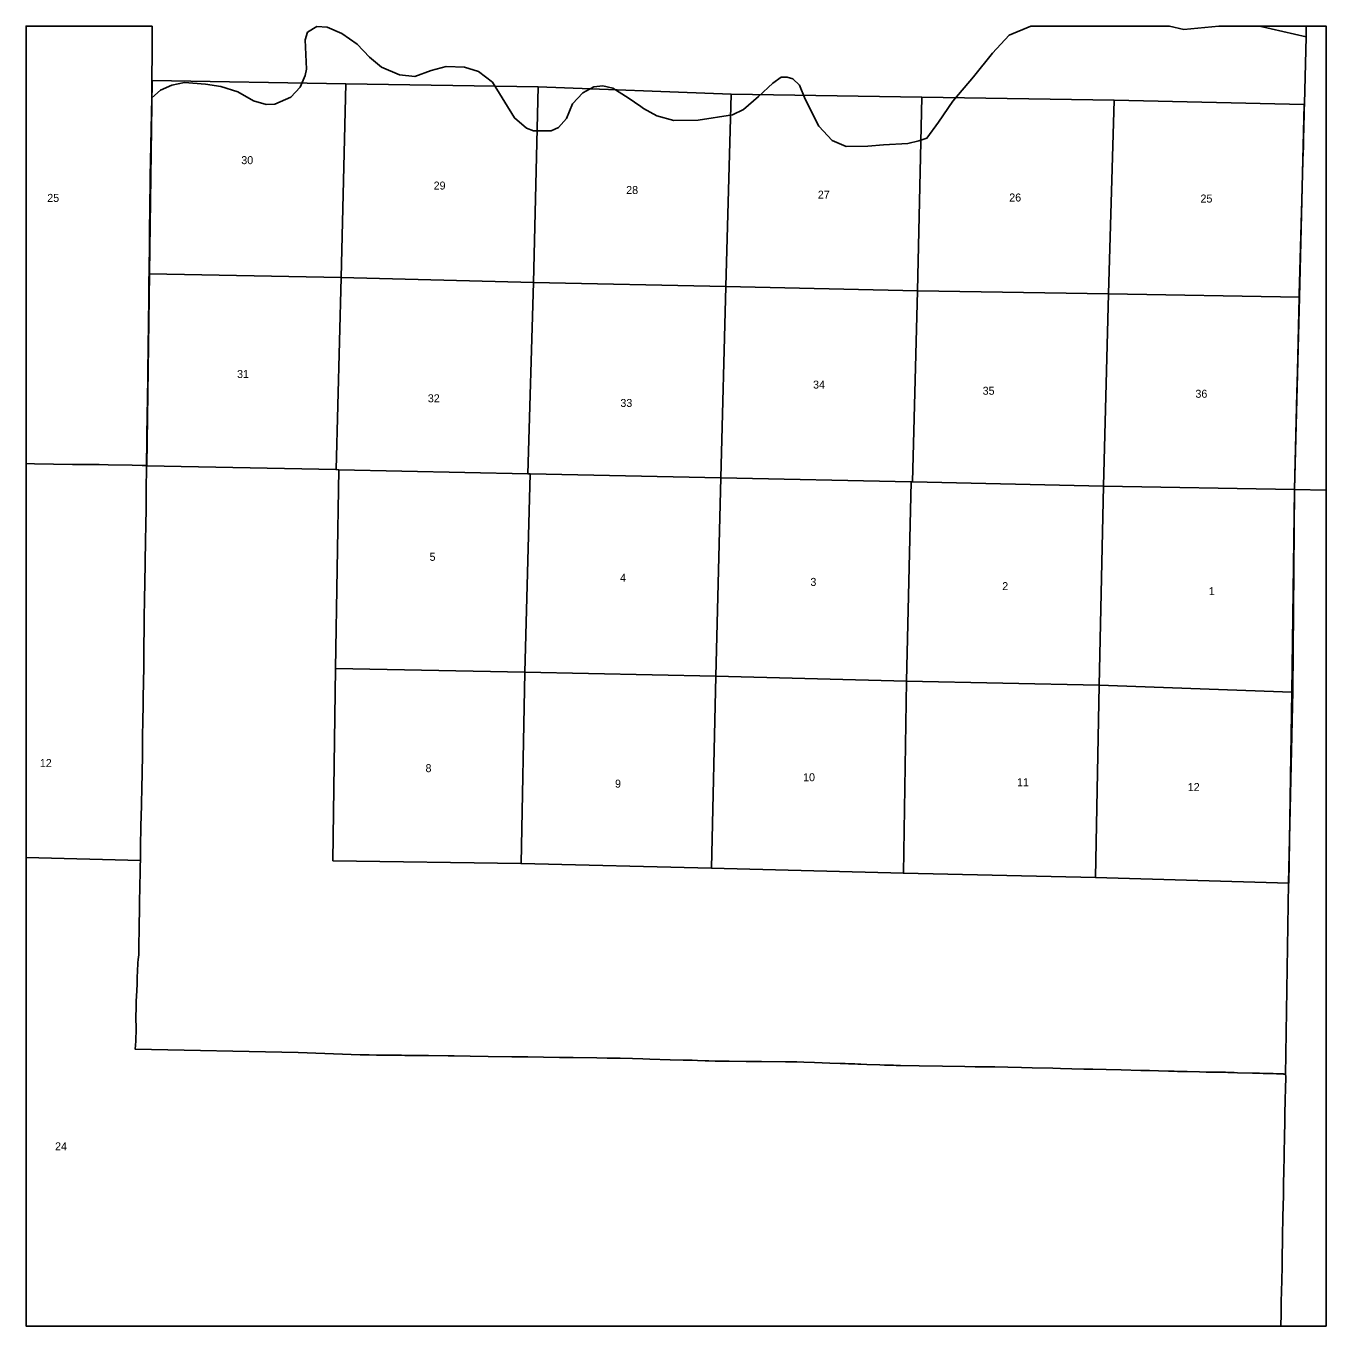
# Model space of a CAD drawing. Extents: x -483 to 680, y 0 to 440.
# Drawn here: x -349.12 to -342.32, y 207.81 to 214.61 of the extents above; entities that cross this region are included whole.
import ezdxf

# ---------------------------------------------------------------- set-up
doc = ezdxf.new("R2010")
doc.units = 0
doc.layers.add('GM_X_Section', color=7, linetype='Continuous')
doc.layers.add('GM_X_Section_Text', color=7, linetype='Continuous')

msp = doc.modelspace()

# ---------------------------------------------------------------- linework, layer by layer
at = {"layer": 'GM_X_Section'}
for points in [[(-348.457, 214.3284), (-347.4432, 214.3104), (-347.4683, 213.2983), (-348.4711, 213.316), (-348.4714, 213.321)], [(-346.4381, 214.2945), (-346.4616, 213.2721), (-347.4683, 213.2983), (-347.4432, 214.3104)], [(-346.4381, 214.2945), (-345.4285, 214.2565), (-345.4554, 213.2508), (-346.4616, 213.2721)], [(-345.4285, 214.2565), (-344.4314, 214.2411), (-344.4539, 213.2286), (-345.4554, 213.2508)], [(-344.4314, 214.2411), (-343.4255, 214.2253), (-343.4546, 213.2125), (-344.4539, 213.2286)], [(-343.4255, 214.2253), (-342.4305, 214.2027), (-342.4564, 213.1951), (-343.4546, 213.2125)], [(-348.4711, 213.316), (-347.4683, 213.2983), (-347.4952, 212.2926), (-348.4844, 212.3116)], [(-347.4683, 213.2983), (-346.4616, 213.2721), (-346.4921, 212.2714), (-347.4805, 212.2919), (-347.4952, 212.2926)], [(-346.4616, 213.2721), (-345.4554, 213.2508), (-345.4819, 212.2505), (-346.48, 212.2712), (-346.4921, 212.2714)], [(-345.4554, 213.2508), (-344.4539, 213.2286), (-344.4807, 212.2293), (-344.4864, 212.2291), (-345.4819, 212.2505)], [(-344.4539, 213.2286), (-343.4546, 213.2125), (-343.4808, 212.2057), (-344.4807, 212.2293)], [(-343.4546, 213.2125), (-342.4564, 213.1951), (-342.4815, 212.1887), (-343.4808, 212.2057)], [(-347.4805, 212.2919), (-346.4921, 212.2714), (-346.48, 212.2712), (-346.5077, 211.2328), (-347.4976, 211.2522)], [(-346.48, 212.2712), (-345.4819, 212.2505), (-345.5088, 211.2116), (-346.5077, 211.2328)], [(-345.4819, 212.2505), (-344.4864, 212.2291), (-344.5112, 211.186), (-345.5088, 211.2116)], [(-344.4864, 212.2291), (-344.4807, 212.2293), (-343.4808, 212.2057), (-343.5033, 211.1644), (-344.5112, 211.186)], [(-343.4808, 212.2057), (-342.4815, 212.1887), (-342.496, 211.1278), (-343.5033, 211.1644)], [(-347.4976, 211.2522), (-346.5077, 211.2328), (-346.5274, 210.2315), (-347.5113, 210.2467)], [(-345.5088, 211.2116), (-345.5305, 210.2074), (-346.5274, 210.2315), (-346.5077, 211.2328)], [(-344.5112, 211.186), (-344.5275, 210.1816), (-345.5305, 210.2074), (-345.5088, 211.2116)], [(-344.5112, 211.186), (-343.5033, 211.1644), (-343.522, 210.159), (-344.5275, 210.1816)], [(-343.5033, 211.1644), (-342.496, 211.1278), (-342.512, 210.1288), (-343.522, 210.159)]]:
    msp.add_lwpolyline(points, close=True, dxfattribs=at)
at = {"layer": 'GM_X_Section_Text'}
for points in [[(-348.4567, 214.6131), (-349.1169, 214.6131), (-349.1169, 212.3238), (-349.0716, 212.3232), (-348.8739, 212.32), (-348.7334, 212.3186), (-348.6868, 212.3179), (-348.5624, 212.3158), (-348.5096, 212.315), (-348.4861, 212.3148), (-348.4862, 212.3371), (-348.4859, 212.3552), (-348.4852, 212.4055), (-348.4848, 212.4304), (-348.4847, 212.4472), (-348.4846, 212.459), (-348.4845, 212.4752), (-348.4844, 212.4832), (-348.484, 212.5146), (-348.4835, 212.5318), (-348.4835, 212.5361), (-348.4825, 212.5939), (-348.4824, 212.6076), (-348.482, 212.6324), (-348.4813, 212.6884), (-348.4805, 212.7518), (-348.479, 212.8519), (-348.4783, 212.8904), (-348.4779, 212.9253), (-348.4773, 212.9669), (-348.4766, 213.0235), (-348.4763, 213.0502), (-348.4758, 213.0807), (-348.4754, 213.1105), (-348.4751, 213.1385), (-348.4746, 213.1814), (-348.4739, 213.2486), (-348.4736, 213.284), (-348.4731, 213.3257), (-348.4725, 213.3698), (-348.4716, 213.4419), (-348.4708, 213.4991), (-348.4705, 213.5333), (-348.4701, 213.5775), (-348.4695, 213.6247), (-348.4688, 213.6788), (-348.4687, 213.7118), (-348.4685, 213.7267), (-348.4682, 213.7422), (-348.4682, 213.7584), (-348.468, 213.7696), (-348.4678, 213.7808), (-348.4675, 213.8044), (-348.4671, 213.8264), (-348.4589, 214.2377), (-348.4573, 214.5737)], [(-343.1357, 214.6131), (-343.8606, 214.6131), (-343.9747, 214.5658), (-344.062, 214.4715), (-344.1608, 214.3472), (-344.268, 214.2201), (-344.3438, 214.1108), (-344.4046, 214.0268), (-344.4464, 214.012), (-344.5046, 213.998), (-344.6311, 213.9921), (-344.7127, 213.984), (-344.8265, 213.9828), (-344.9001, 214.0149), (-344.9703, 214.0896), (-345.0417, 214.2309), (-345.0705, 214.3045), (-345.1062, 214.3367), (-345.1361, 214.3458), (-345.1671, 214.3447), (-345.2097, 214.3136), (-345.2855, 214.2445), (-345.3642, 214.1764), (-345.4217, 214.1476), (-345.601, 214.1198), (-345.7287, 214.1186), (-345.8172, 214.1427), (-345.8872, 214.1815), (-345.9017, 214.1914), (-345.9667, 214.2368), (-346.0473, 214.2874), (-346.1001, 214.3), (-346.1473, 214.2953), (-346.2036, 214.2631), (-346.2587, 214.2055), (-346.2897, 214.1285), (-346.3322, 214.0824), (-346.3701, 214.0652), (-346.4615, 214.0642), (-346.4995, 214.078), (-346.5616, 214.132), (-346.6767, 214.3193), (-346.7492, 214.3756), (-346.8228, 214.3974), (-346.9194, 214.402), (-346.9975, 214.3812), (-347.0837, 214.349), (-347.1631, 214.357), (-347.2574, 214.3971), (-347.3206, 214.45), (-347.3851, 214.5189), (-347.4644, 214.5741), (-347.5424, 214.6073), (-347.5965, 214.6107), (-347.6436, 214.5808), (-347.6562, 214.5406), (-347.6503, 214.3877), (-347.656, 214.3543), (-347.6836, 214.2934), (-347.7318, 214.2416), (-347.8157, 214.2047), (-347.8606, 214.2024), (-347.9261, 214.2219), (-348.0089, 214.2679), (-348.0986, 214.2966), (-348.178, 214.308), (-348.2872, 214.3183), (-348.3539, 214.3044), (-348.4136, 214.2768), (-348.4589, 214.2377), (-348.4671, 213.8264), (-348.4675, 213.8044), (-348.4678, 213.7808), (-348.468, 213.7696), (-348.4682, 213.7584), (-348.4682, 213.7422), (-348.4685, 213.7267), (-348.4687, 213.7118), (-348.4688, 213.6788), (-348.4695, 213.6247), (-348.4701, 213.5775), (-348.4705, 213.5333), (-348.4708, 213.4991), (-348.4716, 213.4419), (-348.4725, 213.3698), (-348.4731, 213.3257), (-348.4736, 213.284), (-348.4739, 213.2486), (-348.4746, 213.1814), (-348.4751, 213.1385), (-348.4754, 213.1105), (-348.4758, 213.0807), (-348.4763, 213.0502), (-348.4766, 213.0235), (-348.4773, 212.9669), (-348.4779, 212.9253), (-348.4783, 212.8904), (-348.479, 212.8519), (-348.4805, 212.7518), (-348.4813, 212.6884), (-348.482, 212.6324), (-348.4824, 212.6076), (-348.4825, 212.5939), (-348.4835, 212.5361), (-348.4835, 212.5318), (-348.484, 212.5146), (-348.4844, 212.4832), (-348.4845, 212.4752), (-348.4846, 212.459), (-348.4847, 212.4472), (-348.4848, 212.4304), (-348.4852, 212.4055), (-348.4859, 212.3552), (-348.4862, 212.3371), (-348.4861, 212.3148), (-348.487, 212.2834), (-348.4878, 212.2089), (-348.4882, 212.1716), (-348.4892, 212.0815), (-348.4903, 212.007), (-348.4917, 211.9169), (-348.4932, 211.8144), (-348.4953, 211.6901), (-348.4964, 211.6249), (-348.498, 211.5069), (-348.5005, 211.3236), (-348.501, 211.2863), (-348.5011, 211.2677), (-348.5012, 211.2589), (-348.5034, 211.101), (-348.5037, 211.0804), (-348.504, 211.0579), (-348.5043, 211.0388), (-348.505, 210.9991), (-348.5055, 210.9689), (-348.5067, 210.9082), (-348.5075, 210.8461), (-348.5084, 210.7933), (-348.5097, 210.7125), (-348.5115, 210.6192), (-348.5127, 210.5539), (-348.515, 210.4639), (-348.5154, 210.4457), (-348.5157, 210.4303), (-348.5161, 210.4126), (-348.5173, 210.3352), (-348.5186, 210.2481), (-348.5192, 210.2219), (-348.5202, 210.1722), (-348.5212, 210.1286), (-348.5233, 210.0135), (-348.5255, 209.889), (-348.5268, 209.805), (-348.5275, 209.7563), (-348.5275, 209.7552), (-348.5282, 209.7428), (-348.5295, 209.7304), (-348.5318, 209.7119), (-348.5328, 209.6995), (-348.5336, 209.6808), (-348.535, 209.6248), (-348.5359, 209.6), (-348.5394, 209.5378), (-348.5403, 209.513), (-348.5412, 209.4725), (-348.5418, 209.4352), (-348.5419, 209.4134), (-348.5417, 209.4072), (-348.5415, 209.3885), (-348.5414, 209.3807), (-348.5413, 209.373), (-348.5415, 209.3512), (-348.5425, 209.3201), (-348.5431, 209.303), (-348.5451, 209.2608), (-347.6934, 209.2431), (-347.3681, 209.2316), (-347.3537, 209.2313), (-347.3211, 209.231), (-347.2844, 209.2306), (-347.2396, 209.2301), (-347.2041, 209.2297), (-347.1523, 209.2292), (-347.1351, 209.2288), (-347.104, 209.2288), (-347.0854, 209.2287), (-347.0521, 209.2284), (-347.0481, 209.2284), (-347.0107, 209.2279), (-346.9081, 209.2265), (-346.877, 209.2257), (-346.793, 209.2248), (-346.6997, 209.2235), (-346.5753, 209.2219), (-346.5529, 209.2216), (-346.4913, 209.2206), (-346.4104, 209.2196), (-346.3264, 209.2181), (-346.2549, 209.2172), (-346.1305, 209.2156), (-346.0776, 209.2146), (-346.0508, 209.2141), (-346.0091, 209.2133), (-345.9438, 209.2115), (-345.891, 209.2103), (-345.8537, 209.2092), (-345.7479, 209.2061), (-345.6795, 209.2041), (-345.6329, 209.2029), (-345.6047, 209.202), (-345.5645, 209.2007), (-345.5449, 209.2003), (-345.5113, 209.1991), (-345.4387, 209.1983), (-345.3497, 209.1972), (-345.2689, 209.1966), (-345.1446, 209.1953), (-345.1284, 209.195), (-345.1037, 209.1947), (-345.0854, 209.1944), (-345.0481, 209.1934), (-344.9924, 209.1918), (-344.9117, 209.1888), (-344.8575, 209.1868), (-344.8316, 209.1859), (-344.8149, 209.1853), (-344.7988, 209.1847), (-344.7815, 209.1839), (-344.7664, 209.1833), (-344.7501, 209.1826), (-344.7195, 209.1813), (-344.6514, 209.1789), (-344.6264, 209.1783), (-344.6109, 209.1777), (-344.6001, 209.1774), (-344.5879, 209.177), (-344.5787, 209.1767), (-344.5649, 209.1763), (-344.5519, 209.1759), (-344.5419, 209.1756), (-344.4446, 209.1737), (-344.3234, 209.1721), (-344.2054, 209.1703), (-344.1526, 209.1695), (-344.05, 209.168), (-343.9817, 209.1665), (-343.9102, 209.165), (-343.8543, 209.1635), (-343.7456, 209.161), (-343.7052, 209.1601), (-343.6462, 209.159), (-343.5841, 209.1572), (-343.5406, 209.1562), (-343.536, 209.1561), (-343.466, 209.1543), (-343.3884, 209.1522), (-343.2859, 209.1497), (-343.2393, 209.1488), (-343.1927, 209.1476), (-343.1399, 209.1463), (-343.1119, 209.1456), (-343.0935, 209.1452), (-343.0778, 209.1449), (-343.0436, 209.144), (-342.9784, 209.1424), (-342.9442, 209.1417), (-342.9225, 209.1414), (-342.907, 209.1412), (-342.8728, 209.1405), (-342.8635, 209.1404), (-342.8418, 209.14), (-342.8297, 209.1396), (-342.8201, 209.1392), (-342.7972, 209.1386), (-342.7798, 209.1381), (-342.7021, 209.1361), (-342.679, 209.1354), (-342.6648, 209.135), (-342.6448, 209.1344), (-342.64, 209.1342), (-342.6245, 209.1339), (-342.6059, 209.1335), (-342.5935, 209.1331), (-342.5759, 209.1327), (-342.5639, 209.1324), (-342.5538, 209.1322), (-342.5437, 209.1319), (-342.5407, 209.1316), (-342.5377, 209.131), (-342.5348, 209.1301), (-342.532, 209.1287), (-342.5303, 209.1274), (-342.529, 209.126), (-342.5122, 210.1297), (-342.4897, 211.1345), (-342.481, 212.1886), (-342.4689, 212.6945), (-342.4662, 212.8072), (-342.457, 213.1942), (-342.457, 213.2091), (-342.457, 213.2101), (-342.4432, 213.7014), (-342.4374, 213.9071), (-342.436, 213.9536), (-342.4354, 213.9766), (-342.4346, 214.0079), (-342.4323, 214.1001), (-342.4321, 214.1072), (-342.4317, 214.1332), (-342.4312, 214.1606), (-342.4309, 214.1766), (-342.4301, 214.2052), (-342.4209, 214.5571), (-342.6641, 214.6131), (-342.8772, 214.6131), (-343.06, 214.5947)], [(-342.4201, 214.6131), (-342.6641, 214.6131), (-342.4209, 214.5571)], [(-342.3169, 212.1852), (-342.3169, 214.6131), (-342.4201, 214.6131), (-342.4209, 214.5571), (-342.4301, 214.2052), (-342.4309, 214.1766), (-342.4312, 214.1606), (-342.4317, 214.1332), (-342.4321, 214.1072), (-342.4323, 214.1001), (-342.4346, 214.0079), (-342.4354, 213.9766), (-342.436, 213.9536), (-342.4374, 213.9071), (-342.4432, 213.7014), (-342.457, 213.2101), (-342.457, 213.2091), (-342.457, 213.1942), (-342.4662, 212.8072), (-342.4689, 212.6945), (-342.481, 212.1886)], [(-349.1169, 212.3238), (-349.1169, 210.2637), (-348.5186, 210.2481), (-348.5173, 210.3352), (-348.5161, 210.4126), (-348.5157, 210.4303), (-348.5154, 210.4457), (-348.515, 210.4639), (-348.5127, 210.5539), (-348.5115, 210.6192), (-348.5097, 210.7125), (-348.5084, 210.7933), (-348.5075, 210.8461), (-348.5067, 210.9082), (-348.5055, 210.9689), (-348.505, 210.9991), (-348.5043, 211.0388), (-348.504, 211.0579), (-348.5037, 211.0804), (-348.5034, 211.101), (-348.5012, 211.2589), (-348.5011, 211.2677), (-348.501, 211.2863), (-348.5005, 211.3236), (-348.498, 211.5069), (-348.4964, 211.6249), (-348.4953, 211.6901), (-348.4932, 211.8144), (-348.4917, 211.9169), (-348.4903, 212.007), (-348.4892, 212.0815), (-348.4882, 212.1716), (-348.4878, 212.2089), (-348.487, 212.2834), (-348.4861, 212.3148), (-348.5096, 212.315), (-348.5624, 212.3158), (-348.6868, 212.3179), (-348.7334, 212.3186), (-348.8739, 212.32), (-349.0716, 212.3232)], [(-342.5531, 207.8131), (-342.3169, 207.8131), (-342.3169, 212.1852), (-342.481, 212.1886), (-342.4897, 211.1345), (-342.5122, 210.1297), (-342.529, 209.126), (-342.5277, 209.1241), (-342.5266, 209.1215), (-342.5263, 209.1184), (-342.5262, 209.1122), (-342.5268, 209.0988), (-342.528, 209.0688), (-342.5285, 209.0501), (-342.5289, 209.0377), (-342.5298, 209.0129), (-342.5301, 209.0014), (-342.5305, 208.988), (-342.531, 208.9663), (-342.5314, 208.9508), (-342.5321, 208.9166), (-342.5324, 208.8937), (-342.5326, 208.8792), (-342.534, 208.8046), (-342.5346, 208.7735), (-342.535, 208.7486), (-342.5358, 208.705), (-342.5363, 208.6832), (-342.5365, 208.6739), (-342.537, 208.6491), (-342.537, 208.6463), (-342.5373, 208.6273), (-342.5375, 208.6055), (-342.5384, 208.5762), (-342.5393, 208.5353), (-342.54, 208.4949), (-342.5424, 208.3862), (-342.5429, 208.3584), (-342.5439, 208.3085), (-342.5443, 208.2867), (-342.5448, 208.2588), (-342.5452, 208.2402), (-342.5458, 208.1967), (-342.5461, 208.1625), (-342.5469, 208.1242), (-342.5486, 208.0506), (-342.5508, 207.9388), (-342.5521, 207.8684), (-342.553, 207.8207)], [(-349.1169, 210.2637), (-349.1169, 207.8131), (-342.5531, 207.8131), (-342.553, 207.8207), (-342.5521, 207.8684), (-342.5508, 207.9388), (-342.5486, 208.0506), (-342.5469, 208.1242), (-342.5461, 208.1625), (-342.5458, 208.1967), (-342.5452, 208.2402), (-342.5448, 208.2588), (-342.5443, 208.2867), (-342.5439, 208.3085), (-342.5429, 208.3584), (-342.5424, 208.3862), (-342.54, 208.4949), (-342.5393, 208.5353), (-342.5384, 208.5762), (-342.5375, 208.6055), (-342.5373, 208.6273), (-342.537, 208.6463), (-342.537, 208.6491), (-342.5365, 208.6739), (-342.5363, 208.6832), (-342.5358, 208.705), (-342.535, 208.7486), (-342.5346, 208.7735), (-342.534, 208.8046), (-342.5326, 208.8792), (-342.5324, 208.8937), (-342.5321, 208.9166), (-342.5314, 208.9508), (-342.531, 208.9663), (-342.5305, 208.988), (-342.5301, 209.0014), (-342.5298, 209.0129), (-342.5289, 209.0377), (-342.5285, 209.0501), (-342.528, 209.0688), (-342.5268, 209.0988), (-342.5262, 209.1122), (-342.5263, 209.1184), (-342.5266, 209.1215), (-342.5277, 209.1241), (-342.529, 209.126), (-342.5303, 209.1274), (-342.532, 209.1287), (-342.5348, 209.1301), (-342.5377, 209.131), (-342.5407, 209.1316), (-342.5437, 209.1319), (-342.5538, 209.1322), (-342.5639, 209.1324), (-342.5759, 209.1327), (-342.5935, 209.1331), (-342.6059, 209.1335), (-342.6245, 209.1339), (-342.64, 209.1342), (-342.6448, 209.1344), (-342.6648, 209.135), (-342.679, 209.1354), (-342.7021, 209.1361), (-342.7798, 209.1381), (-342.7972, 209.1386), (-342.8201, 209.1392), (-342.8297, 209.1396), (-342.8418, 209.14), (-342.8635, 209.1404), (-342.8728, 209.1405), (-342.907, 209.1412), (-342.9225, 209.1414), (-342.9442, 209.1417), (-342.9784, 209.1424), (-343.0436, 209.144), (-343.0778, 209.1449), (-343.0935, 209.1452), (-343.1119, 209.1456), (-343.1399, 209.1463), (-343.1927, 209.1476), (-343.2393, 209.1488), (-343.2859, 209.1497), (-343.3884, 209.1522), (-343.466, 209.1543), (-343.536, 209.1561), (-343.5406, 209.1562), (-343.5841, 209.1572), (-343.6462, 209.159), (-343.7052, 209.1601), (-343.7456, 209.161), (-343.8543, 209.1635), (-343.9102, 209.165), (-343.9817, 209.1665), (-344.05, 209.168), (-344.1526, 209.1695), (-344.2054, 209.1703), (-344.3234, 209.1721), (-344.4446, 209.1737), (-344.5419, 209.1756), (-344.5519, 209.1759), (-344.5649, 209.1763), (-344.5787, 209.1767), (-344.5879, 209.177), (-344.6001, 209.1774), (-344.6109, 209.1777), (-344.6264, 209.1783), (-344.6514, 209.1789), (-344.7195, 209.1813), (-344.7501, 209.1826), (-344.7664, 209.1833), (-344.7815, 209.1839), (-344.7988, 209.1847), (-344.8149, 209.1853), (-344.8316, 209.1859), (-344.8575, 209.1868), (-344.9117, 209.1888), (-344.9924, 209.1918), (-345.0481, 209.1934), (-345.0854, 209.1944), (-345.1037, 209.1947), (-345.1284, 209.195), (-345.1446, 209.1953), (-345.2689, 209.1966), (-345.3497, 209.1972), (-345.4387, 209.1983), (-345.5113, 209.1991), (-345.5449, 209.2003), (-345.5645, 209.2007), (-345.6047, 209.202), (-345.6329, 209.2029), (-345.6795, 209.2041), (-345.7479, 209.2061), (-345.8537, 209.2092), (-345.891, 209.2103), (-345.9438, 209.2115), (-346.0091, 209.2133), (-346.0508, 209.2141), (-346.0776, 209.2146), (-346.1305, 209.2156), (-346.2549, 209.2172), (-346.3264, 209.2181), (-346.4104, 209.2196), (-346.4913, 209.2206), (-346.5529, 209.2216), (-346.5753, 209.2219), (-346.6997, 209.2235), (-346.793, 209.2248), (-346.877, 209.2257), (-346.9081, 209.2265), (-347.0107, 209.2279), (-347.0481, 209.2284), (-347.0521, 209.2284), (-347.0854, 209.2287), (-347.104, 209.2288), (-347.1351, 209.2288), (-347.1523, 209.2292), (-347.2041, 209.2297), (-347.2396, 209.2301), (-347.2844, 209.2306), (-347.3211, 209.231), (-347.3537, 209.2313), (-347.3681, 209.2316), (-347.6934, 209.2431), (-348.5451, 209.2608), (-348.5431, 209.303), (-348.5425, 209.3201), (-348.5415, 209.3512), (-348.5413, 209.373), (-348.5414, 209.3807), (-348.5415, 209.3885), (-348.5417, 209.4072), (-348.5419, 209.4134), (-348.5418, 209.4352), (-348.5412, 209.4725), (-348.5403, 209.513), (-348.5394, 209.5378), (-348.5359, 209.6), (-348.535, 209.6248), (-348.5336, 209.6808), (-348.5328, 209.6995), (-348.5318, 209.7119), (-348.5295, 209.7304), (-348.5282, 209.7428), (-348.5275, 209.7552), (-348.5275, 209.7563), (-348.5268, 209.805), (-348.5255, 209.889), (-348.5233, 210.0135), (-348.5212, 210.1286), (-348.5202, 210.1722), (-348.5192, 210.2219), (-348.5186, 210.2481)]]:
    msp.add_lwpolyline(points, close=True, dxfattribs=at)

# ---------------------------------------------------------------- texts
for s, height, p in [('30', 0.04186, (-347.9908, 213.8905)), ('29', 0.04186, (-346.9846, 213.7576)), ('25', 0.04186, (-349.0058, 213.693)), ('28', 0.04186, (-345.9775, 213.7343)), ('27', 0.04186, (-344.975, 213.7101)), ('26', 0.04186, (-343.9738, 213.6951)), ('25', 0.04186, (-342.9734, 213.6897)), ('31', 0.04186, (-348.0129, 212.7718)), ('34', 0.04186, (-345, 212.7164)), ('35', 0.04186, (-344.1129, 212.6843)), ('36', 0.04186, (-343, 212.6685)), ('32', 0.04186, (-347.015, 212.6447)), ('33', 0.04186, (-346.0079, 212.6205)), ('5', 0.0419, (-347.0059, 211.8156)), ('4', 0.0419, (-346.0096, 211.7063)), ('3', 0.0419, (-345.0138, 211.6843)), ('2', 0.0419, (-344.0104, 211.6621)), ('1', 0.0419, (-342.93, 211.636)), ('12', 0.04186, (-349.0445, 210.7369)), ('8', 0.0419, (-347.0271, 210.7101)), ('9', 0.0419, (-346.0359, 210.6289)), ('10', 0.04186, (-345.0521, 210.6626)), ('11', 0.04186, (-343.9329, 210.6368)), ('12', 0.04186, (-343.04, 210.6113)), ('24', 0.04186, (-348.9649, 208.7319))]:
    msp.add_text(s, height=height, rotation=0.00001, dxfattribs=at).set_placement(p)

doc.saveas('drawing.dxf')
